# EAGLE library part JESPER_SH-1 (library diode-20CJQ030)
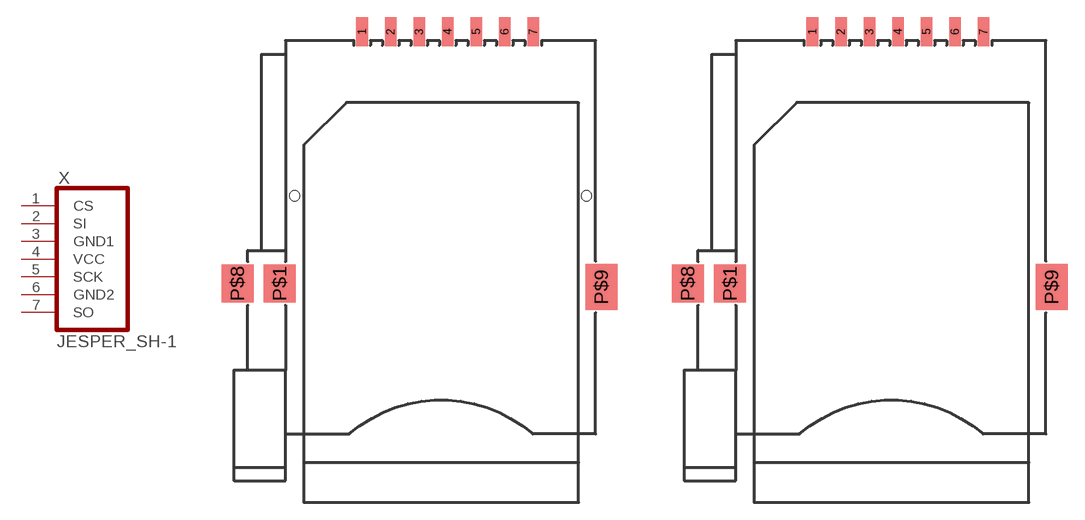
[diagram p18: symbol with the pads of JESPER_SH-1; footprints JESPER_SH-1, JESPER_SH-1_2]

Designator prefix X

## JESPER_SH-1  [JESPER_SH-1]
1  CS
2  SI
3  GND1  pwr
4  VCC  pwr
5  SCK
6  GND2  pwr
7  SO

## JESPER_SH-1A  [JESPER_SH-1_2]
Pads as for JESPER_SH-1

## Footprint JESPER_SH-1 (pad centres in mm)
smd 1.016 x 2.54: 1 -6.875,22.096; 2 -4.375,22.096; 3 -1.875,22.096; 4 0.625,22.096; 5 3.125,22.096; 6 5.625,22.096; 7 8.125,22.096
smd 2.8 x 3.3: P$1 -14.1,0; P$8 -17.8,0
smd 2.8 x 4: P$9 14.1,-0.3
hole 0.9 at -12.8,7.7
hole 0.9 at 12.8,7.7

## Footprint JESPER_SH-1_2 (pad centres in mm)
smd 1.016 x 2.54: 1 -6.875,20.826; 2 -4.375,20.826; 3 -1.875,20.826; 4 0.625,20.826; 5 3.125,20.826; 6 5.625,20.826; 7 8.125,20.826
smd 2.8 x 3.3: P$1 -14.1,-1.27; P$8 -17.8,-1.27
smd 2.8 x 4: P$9 14.1,-1.57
